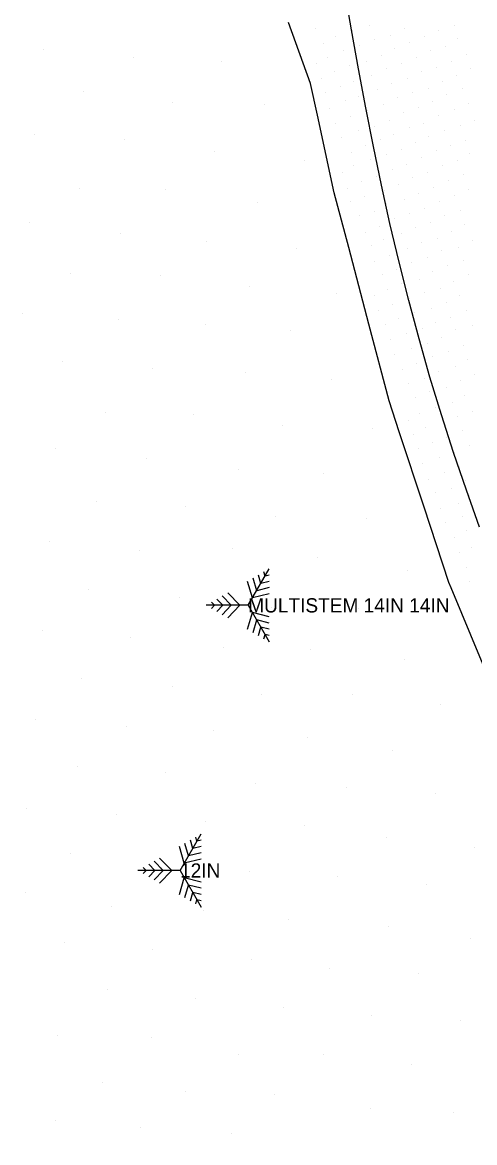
# Model space of a CAD drawing. Extents: x 1732346 to 1733076, y 467730 to 468633.
# Drawn here: x 1732627.1 to 1732684.2, y 468189.3 to 468330.7 of the extents above; entities that cross this region are included whole.
import ezdxf

# ---------------------------------------------------------------- set-up
doc = ezdxf.new("R2010")
doc.units = 0
for name, color, linetype in [('Default', 7, 'Continuous'), ('S_Ground_SpotElevation', 7, 'Continuous'), ('S_Roadway_Edge_Pavement', 7, 'Continuous'), ('S_Roadway_Painted_Lines', 7, 'Continuous'), ('S_Text', 7, 'Continuous'), ('S_Trees_Conifer_Pay', 7, 'Continuous')]:
    doc.layers.add(name, color=color, linetype=linetype)

# ---------------------------------------------------------------- blocks, each defined once
blk = doc.blocks.new('POINT_DISPLAY')
at = {"layer": 'Default'}
blk.add_line((0, 0), (0, 0), dxfattribs=at)

msp = doc.modelspace()

# ---------------------------------------------------------------- linework, layer by layer
at = {"layer": 'S_Roadway_Edge_Pavement'}
msp.add_lwpolyline([(1732721.39, 468184.76), (1732715.91, 468193.13), (1732711.3, 468200.17), (1732706.18, 468208.76), (1732701.05, 468217.34), (1732699.3, 468220.27), (1732694.79, 468229.2), (1732690.28, 468238.12), (1732688.89, 468240.87), (1732685.04, 468250.1), (1732681.2, 468259.33), (1732680.92, 468260), (1732677.79, 468269.5), (1732674.66, 468279), (1732673.37, 468282.92), (1732670.82, 468292.59), (1732668.27, 468302.26), (1732666.45, 468309.17), (1732664.33, 468318.94), (1732663.46, 468322.93), (1732660.65, 468330.66)], dxfattribs=at)
at = {"layer": 'S_Roadway_Painted_Lines'}
msp.add_lwpolyline([(1732684.8, 468266.97), (1732683.12, 468271.65), (1732681.5, 468276.37), (1732679.97, 468281.14), (1732678.53, 468285.88), (1732677.15, 468290.72), (1732675.85, 468295.57), (1732674.63, 468300.4), (1732673.48, 468305.27), (1732672.42, 468310.11), (1732671.41, 468314.98), (1732670.43, 468319.88), (1732669.51, 468324.79), (1732668.62, 468329.73), (1732667.8, 468334.62)], dxfattribs=at)
at = {"layer": 'S_Trees_Conifer_Pay'}
for p, q in [((1732655.58, 468257.11), (1732658.24, 468261.72)), ((1732657.18, 468259.87), (1732656.88, 468260.92)), ((1732657.71, 468260.79), (1732657.56, 468261.32)), ((1732658.24, 468260.92), (1732657.71, 468260.79)), ((1732656.11, 468258.03), (1732655.51, 468260.13)), ((1732656.65, 468258.95), (1732656.19, 468260.53)), ((1732658.24, 468260.13), (1732657.18, 468259.87)), ((1732653.45, 468257.11), (1732652.31, 468258.29)), ((1732654.52, 468257.11), (1732653, 468258.69)), ((1732658.24, 468258.55), (1732656.11, 468258.03)), ((1732658.24, 468259.35), (1732656.65, 468258.95)), ((1732655.58, 468257.11), (1732650.26, 468257.11)), ((1732651.32, 468257.11), (1732650.94, 468257.5)), ((1732650.94, 468256.71), (1732651.32, 468257.11)), ((1732652.39, 468257.11), (1732651.63, 468257.89)), ((1732651.63, 468256.31), (1732652.39, 468257.11)), ((1732652.31, 468255.92), (1732653.45, 468257.11)), ((1732653, 468255.52), (1732654.52, 468257.11)), ((1732655.58, 468257.11), (1732658.24, 468252.49)), ((1732655.51, 468254.08), (1732656.11, 468256.18)), ((1732658.24, 468255.66), (1732656.11, 468256.18)), ((1732656.19, 468253.68), (1732656.65, 468255.26)), ((1732658.24, 468254.86), (1732656.65, 468255.26)), ((1732656.88, 468253.28), (1732657.18, 468254.34)), ((1732658.24, 468254.08), (1732657.18, 468254.34)), ((1732657.56, 468252.89), (1732657.71, 468253.42)), ((1732658.24, 468253.28), (1732657.71, 468253.42)), ((1732646.98, 468223.64), (1732649.65, 468228.25)), ((1732648.05, 468225.49), (1732647.59, 468227.07)), ((1732648.58, 468226.41), (1732648.28, 468227.46)), ((1732649.11, 468227.33), (1732648.96, 468227.86)), ((1732649.65, 468227.46), (1732649.11, 468227.33)), ((1732647.51, 468224.57), (1732646.91, 468226.67)), ((1732649.65, 468225.88), (1732648.05, 468225.49)), ((1732649.65, 468226.67), (1732648.58, 468226.41)), ((1732643.79, 468223.64), (1732643.03, 468224.43)), ((1732644.85, 468223.64), (1732643.71, 468224.83)), ((1732645.92, 468223.64), (1732644.4, 468225.22)), ((1732649.65, 468225.09), (1732647.51, 468224.57)), ((1732646.98, 468223.64), (1732641.66, 468223.64)), ((1732642.72, 468223.64), (1732642.34, 468224.04)), ((1732642.34, 468223.25), (1732642.72, 468223.64)), ((1732643.03, 468222.85), (1732643.79, 468223.64)), ((1732643.71, 468222.46), (1732644.85, 468223.64)), ((1732644.4, 468222.06), (1732645.92, 468223.64)), ((1732646.98, 468223.64), (1732649.65, 468219.03)), ((1732646.91, 468220.61), (1732647.51, 468222.72)), ((1732649.65, 468222.19), (1732647.51, 468222.72)), ((1732647.59, 468220.22), (1732648.05, 468221.8)), ((1732649.65, 468221.4), (1732648.05, 468221.8)), ((1732648.28, 468219.82), (1732648.58, 468220.88)), ((1732649.65, 468220.61), (1732648.58, 468220.88)), ((1732648.96, 468219.43), (1732649.11, 468219.96)), ((1732649.65, 468219.82), (1732649.11, 468219.96))]:
    msp.add_line(p, q, dxfattribs=at)

# ---------------------------------------------------------------- block references
at = {"layer": 'S_Ground_SpotElevation'}
for p in [(1732670.89, 468330.21), (1732681.6, 468330.24), (1732664.13, 468329.95), (1732666.66, 468328.88), (1732668.72, 468329.65), (1732673.49, 468328.99), (1732675.32, 468329.92), (1732677.89, 468328.84), (1732679.61, 468329.63), (1732665.05, 468327.98), (1732669.63, 468327.79), (1732671.56, 468328.5), (1732675.96, 468328.12), (1732680.53, 468327.57), (1732682.04, 468328.59), (1732629.78, 468327.2), (1732641.15, 468326.29), (1732665.62, 468326.2), (1732667.55, 468327.11), (1732672.35, 468326.52), (1732674.07, 468327.31), (1732676.83, 468326.18), (1732678.54, 468327.05), (1732683.08, 468326.65), (1732652.2, 468325.74), (1732664.17, 468325.46), (1732668.42, 468325.22), (1732670.5, 468325.67), (1732673, 468324.82), (1732674.94, 468325.46), (1732679.39, 468324.94), (1732681.27, 468325.76), (1732683.62, 468324.79), (1732664.82, 468323.63), (1732666.46, 468324.49), (1732668.85, 468323.18), (1732671.19, 468324.01), (1732675.7, 468323.56), (1732677.42, 468324.43), (1732680.09, 468323.16), (1732681.93, 468323.9), (1732634.77, 468321.91), (1732665.28, 468321.84), (1732667.25, 468322.62), (1732671.94, 468322.15), (1732673.71, 468322.99), (1732676.28, 468321.79), (1732678.3, 468322.38), (1732682.59, 468322.29), (1732646.05, 468320.53), (1732657.63, 468320.28), (1732667.88, 468320.76), (1732669.55, 468321.31), (1732674.42, 468321.16), (1732678.87, 468320.74), (1732680.66, 468321.51), (1732683.37, 468320.39), (1732665.9, 468319.85), (1732670.68, 468319.6), (1732672.68, 468320.27), (1732675.18, 468319.28), (1732677.08, 468319.94), (1732679.59, 468318.92), (1732681.57, 468319.63), (1732666.63, 468317.85), (1732668.48, 468318.79), (1732671.53, 468317.53), (1732673.38, 468318.32), (1732677.68, 468317.95), (1732682.36, 468317.64), (1732684.12, 468318.28), (1732628.6, 468316.48), (1732667.38, 468316.18), (1732669.53, 468317), (1732673.94, 468316.57), (1732676, 468317.34), (1732678.32, 468316.25), (1732680.39, 468317.03), (1732639.97, 468315.82), (1732670.44, 468315.12), (1732672.22, 468315.87), (1732674.97, 468314.65), (1732676.7, 468315.5), (1732681.12, 468315.12), (1732683, 468315.81), (1732651.32, 468314.41), (1732662.74, 468313.24), (1732668.61, 468314.3), (1732671.08, 468313.3), (1732673, 468314.04), (1732677.47, 468313.67), (1732679.33, 468314.45), (1732682.02, 468313.22), (1732683.55, 468314.14), (1732668.92, 468312.56), (1732673.85, 468312.12), (1732675.6, 468312.72), (1732680.08, 468312.58), (1732667.52, 468311.73), (1732669.84, 468310.62), (1732671.75, 468311.25), (1732676.28, 468311.03), (1732678.19, 468311.72), (1732680.86, 468310.69), (1732682.7, 468311.46), (1732634.29, 468309.73), (1732645.16, 468309.59), (1732668.11, 468309.76), (1732672.74, 468309.48), (1732674.55, 468310.23), (1732677.08, 468309.11), (1732679.03, 468309.82), (1732683.42, 468309.57), (1732656.79, 468307.91), (1732668.54, 468308.05), (1732670.32, 468308.72), (1732673.08, 468307.79), (1732675.34, 468308.35), (1732679.75, 468308.09), (1732681.59, 468308.82), (1732669.64, 468306.23), (1732671.47, 468306.76), (1732675.92, 468306.6), (1732677.82, 468307.12), (1732680.31, 468306.33), (1732682.39, 468306.91), (1732627.92, 468305.46), (1732672.2, 468304.9), (1732674.04, 468305.91), (1732676.64, 468304.8), (1732678.61, 468305.45), (1732682.95, 468305.15), (1732639.46, 468304), (1732670.39, 468304.19), (1732674.93, 468304), (1732679.46, 468303.45), (1732681.29, 468304.29), (1732650.37, 468303.05), (1732661.72, 468302.11), (1732671.1, 468302.52), (1732672.64, 468303.3), (1732675.69, 468302.11), (1732677.42, 468302.92), (1732682.08, 468302.31), (1732683.88, 468303.16), (1732673.44, 468301.29), (1732678.18, 468301.05), (1732679.96, 468301.83), (1732682.79, 468300.59), (1732671.58, 468300.48), (1732674.26, 468299.49), (1732676.15, 468300.37), (1732678.9, 468299.24), (1732680.76, 468299.95), (1732633.18, 468299.02), (1732644.49, 468298.67), (1732672.49, 468298.8), (1732674.95, 468297.71), (1732677.18, 468298.2), (1732681.51, 468297.99), (1732683.42, 468298.81), (1732655.72, 468297.38), (1732666.77, 468296.4), (1732673.15, 468296.99), (1732677.9, 468296.57), (1732679.84, 468297.11), (1732682.23, 468296.26), (1732671.58, 468296.2), (1732673.77, 468295.06), (1732675.99, 468295.8), (1732680.56, 468295.34), (1732627.07, 468293.99), (1732672.05, 468294.32), (1732676.6, 468294.03), (1732678.74, 468294.56), (1732681.11, 468293.43), (1732683.08, 468294.36), (1732639.22, 468293.22), (1732650.19, 468292.51), (1732672.88, 468292.52), (1732674.57, 468293.26), (1732677.61, 468292.03), (1732679.28, 468292.83), (1732683.85, 468292.42), (1732660.96, 468291.77), (1732673.54, 468290.61), (1732675.55, 468291.43), (1732680.04, 468290.92), (1732681.75, 468291.85), (1732676.17, 468289.54), (1732678.23, 468290.17), (1732682.73, 468289.88), (1732632.15, 468287.83), (1732674.08, 468288.71), (1732678.8, 468288.45), (1732680.89, 468289.15), (1732683.26, 468288.07), (1732643.45, 468287.01), (1732655.23, 468286.52), (1732675.04, 468286.84), (1732676.87, 468287.6), (1732679.63, 468286.63), (1732681.69, 468287.23), (1732666.08, 468285.56), (1732675.88, 468285.04), (1732677.9, 468285.73), (1732682.37, 468285.46), (1732684.09, 468286.28), (1732678.44, 468284.04), (1732680.57, 468284.63), (1732682.91, 468283.59), (1732676.67, 468283.29), (1732681.32, 468282.75), (1732637.59, 468281.42), (1732648.62, 468281.2), (1732677.18, 468281.29), (1732679.22, 468282.04), (1732682, 468280.89), (1732683.92, 468281.5), (1732659.88, 468279.76), (1732671.21, 468279.42), (1732675.79, 468280.41), (1732678.01, 468279.52), (1732680.18, 468280.2), (1732676.49, 468278.67), (1732680.61, 468278.23), (1732682.66, 468279.18), (1732631.27, 468276.93), (1732677.1, 468276.83), (1732678.81, 468277.63), (1732683.5, 468277.28), (1732642.68, 468275.64), (1732679.74, 468275.73), (1732681.68, 468276.43), (1732654.33, 468274.18), (1732665.05, 468273.7), (1732677.58, 468275.03), (1732680.42, 468273.89), (1732682.3, 468274.64), (1732678.28, 468272.98), (1732683.04, 468272.8), (1732679.18, 468271.39), (1732681.24, 468271.85), (1732683.56, 468271), (1732636.45, 468270.21), (1732647.67, 468269.59), (1732682.07, 468269.96), (1732659.06, 468268.26), (1732670.48, 468268.02), (1732679.87, 468269.38), (1732682.62, 468268.34), (1732680.55, 468267.57), (1732630.52, 468265.15), (1732681.58, 468265.66), (1732683.18, 468266.55), (1732641.81, 468264), (1732653.55, 468264.27), (1732682.27, 468263.82), (1732683.74, 468264.46), (1732664.3, 468263.12), (1732675.72, 468261.56), (1732683.08, 468261.83), (1732683.47, 468260.11), (1732635.46, 468259.04), (1732646.87, 468258.05), (1732658.56, 468256.86), (1732669.45, 468256.73), (1732629.64, 468253.89), (1732640.7, 468253.09), (1732652.43, 468251.8), (1732663.42, 468251.58), (1732675.25, 468250.31), (1732634.59, 468247.88), (1732645.99, 468246.8), (1732657.32, 468245.84), (1732668.8, 468245.84), (1732679.92, 468244.58), (1732628.72, 468242.72), (1732640.2, 468241.87), (1732651.26, 468241.33), (1732663.06, 468240.43), (1732673.76, 468238.77), (1732634.05, 468236.71), (1732645.1, 468236), (1732656.46, 468234.56), (1732667.95, 468234.17), (1732679.23, 468233.37), (1732627.62, 468231.47), (1732638.92, 468230.71), (1732650.22, 468229.89), (1732662.7, 468229.37), (1732673.04, 468227.78), (1732633.18, 468225.83), (1732684.15, 468226.53), (1732644.65, 468224.01), (1732655.74, 468223.49), (1732666.9, 468222.95), (1732678.05, 468221.89), (1732627.52, 468220.9), (1732638.33, 468219.07), (1732649.97, 468218.65), (1732660.73, 468217.44), (1732673.35, 468216.64), (1732632.34, 468214.53), (1732683.6, 468215.12), (1732643.56, 468213.71), (1732656.03, 468212.38), (1732665.8, 468211.31), (1732677.07, 468210.71), (1732637.83, 468208.6), (1732648.87, 468207.55), (1732660.03, 468206.33), (1732671.17, 468205.37), (1732682.34, 468204.69), (1732631.55, 468202.86), (1732643.38, 468202.55), (1732654.4, 468200.48), (1732665.11, 468200.47), (1732676.25, 468199.16), (1732637.22, 468196.95), (1732647.62, 468195.7), (1732658.92, 468195.32), (1732671.03, 468193.62), (1732631.23, 468192.1), (1732681.5, 468193.05), (1732641.95, 468191.22), (1732653.48, 468190.41)]:
    msp.add_blockref('POINT_DISPLAY', p, dxfattribs=at)

# ---------------------------------------------------------------- texts
at = {"layer": 'S_Text'}
for s, p in [('MULTISTEM 14IN 14IN', (1732655.58, 468256.2)), ('12IN', (1732646.98, 468222.74))]:
    msp.add_text(s, height=1.8, dxfattribs=at).set_placement(p)

doc.saveas('drawing.dxf')
